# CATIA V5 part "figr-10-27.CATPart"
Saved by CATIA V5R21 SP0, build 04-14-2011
Part number: Part1
Bounding box of the stored display mesh (mm): x -60 to 70, y 0 to 100.393, z 0 to 0
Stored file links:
  D:\CATIA V5R21 E-RESOURCES\CATIA-V5R21\catia-v5r21-prt\c10-catia-v5r20-prt\c10-catia-v5r21-figr-10-27.CATPart
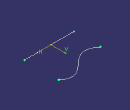
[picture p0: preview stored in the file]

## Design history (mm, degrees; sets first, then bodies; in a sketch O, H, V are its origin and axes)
Body1 (main body)
  Sketch1 on xy-plane, origin (0, 0, 0), H (1, 0, 0), V (0, 1, 0)
    line L1 (-60, 0) -> (70, 0)
    point P1 (-60, 0)
    coincidence: P1 H
    horizontal: L1 H
  Sketch2 on xy-plane, origin (0, 0, 0), H (1, 0, 0), V (0, 1, 0)
    spline S1 through (-60, 70) (-20, 60) (40, 100) (70, 90)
